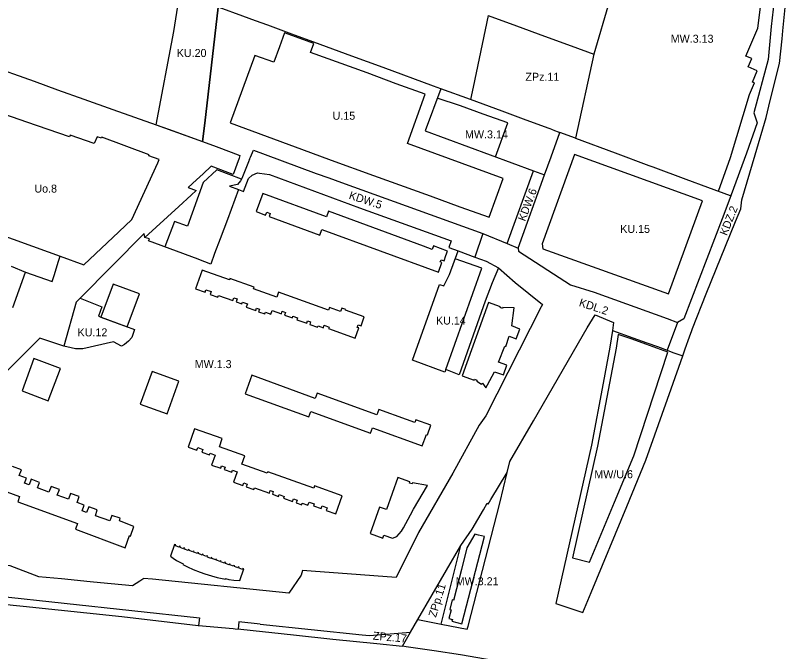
# Model space of a CAD drawing. Extents: x 7428239 to 7429836, y 5549133 to 5550853.
# Drawn here: x 7429012.7 to 7429496.4, y 5549348.1 to 5549745.6 of the extents above; entities that cross this region are included whole.
import ezdxf

# ---------------------------------------------------------------- set-up
doc = ezdxf.new("R2010")
doc.units = 0
for name, color, linetype in [('LIN_linie rozgraniczające', 7, 'Continuous'), ('LIN_nieprzekraczalna linia zabudowy', 7, 'Continuous'), ('LIN_obowiązująca linia zabudowy', 7, 'Continuous'), ('TXT_Oznaczenia Przeznaczenia', 7, 'Continuous')]:
    doc.layers.add(name, color=color, linetype=linetype)

msp = doc.modelspace()

# ---------------------------------------------------------------- linework, layer by layer
at = {"layer": 'LIN_linie rozgraniczające'}
for p, q in [((7429492.21, 5549735.89), (7429496.38, 5549776.96)), ((7429383.84, 5549754.68), (7429374.1, 5549721.36)), ((7429139.27, 5549750.82), (7429131.04, 5549678.2)), ((7429162.7, 5549742.24), (7429154.81, 5549745.13)), ((7429170.29, 5549739.46), (7429162.7, 5549742.24)), ((7429185.31, 5549733.96), (7429170.29, 5549739.46)), ((7429203.15, 5549727.43), (7429185.31, 5549733.96)), ((7429491.7, 5549730.91), (7429492.21, 5549735.89)), ((7429490.14, 5549715.52), (7429491.7, 5549730.91)), ((7429222.87, 5549720.22), (7429203.15, 5549727.43)), ((7429242.43, 5549713.03), (7429222.87, 5549720.22)), ((7429374.1, 5549721.36), (7429362.73, 5549668.82)), ((7429484.37, 5549692.54), (7429490.14, 5549715.52)), ((7429273.96, 5549701.46), (7429242.43, 5549713.03)), ((7429278.42, 5549699.82), (7429268.77, 5549673.56)), ((7429278.42, 5549699.82), (7429273.96, 5549701.46)), ((7429481.71, 5549681.92), (7429484.37, 5549692.54)), ((7429331.75, 5549680.24), (7429316.79, 5549685.74)), ((7429346.1, 5549674.98), (7429331.75, 5549680.24)), ((7429474.87, 5549658.58), (7429481.71, 5549681.92)), ((7429131.04, 5549678.2), (7429129.64, 5549666.8)), ((7429348.48, 5549674.09), (7429346.1, 5549674.98)), ((7429268.77, 5549673.56), (7429336.45, 5549648.48)), ((7429347.4, 5549657.15), (7429352.93, 5549672.44)), ((7429348.48, 5549674.09), (7429352.93, 5549672.44)), ((7429362.73, 5549668.82), (7429352.93, 5549672.44)), ((7429343.37, 5549646), (7429347.4, 5549657.15)), ((7429466.6, 5549630.37), (7429474.87, 5549658.58)), ((7429326.78, 5549600.18), (7429343.37, 5549646)), ((7429336.45, 5549648.48), (7429343.37, 5549646)), ((7429465.94, 5549624.78), (7429466.6, 5549630.37)), ((7429462.67, 5549616.76), (7429465.94, 5549624.78)), ((7428972.53, 5549619.83), (7429033.1, 5549597.79)), ((7429444.27, 5549571.62), (7429462.67, 5549616.76)), ((7429304.83, 5549609.32), (7429299.82, 5549594.64)), ((7429319.91, 5549603.04), (7429326.78, 5549600.18)), ((7429033.1, 5549597.79), (7429040.61, 5549595.06)), ((7429283.91, 5549583.75), (7429289.35, 5549598.4)), ((7429010.07, 5549588.99), (7429018.99, 5549585.19)), ((7429314.53, 5549587.88), (7429310.67, 5549578.44)), ((7429280.29, 5549576.52), (7429283.91, 5549583.75)), ((7429310.67, 5549578.44), (7429306.18, 5549567.03)), ((7429260.89, 5549530.11), (7429277.63, 5549577.44)), ((7429277.63, 5549577.44), (7429280.29, 5549576.52)), ((7429306.18, 5549567.03), (7429289.94, 5549520.95)), ((7429341.24, 5549563.45), (7429306.6, 5549495.47)), ((7429426.47, 5549553.73), (7429420, 5549536.31)), ((7429433.84, 5549544.68), (7429435.4, 5549548.7)), ((7429281.03, 5549522.62), (7429260.89, 5549530.11)), ((7429281.61, 5549524.26), (7429281.03, 5549522.62)), ((7429289.94, 5549520.95), (7429281.61, 5549524.26)), ((7429306.6, 5549495.47), (7429302.38, 5549489.44))]:
    msp.add_line(p, q, dxfattribs=at)
for points in [[(7429489.37, 5549782.19), (7429486.1, 5549749.51), (7429484.91, 5549738.63), (7429483.01, 5549718.14), (7429474.16, 5549684.69), (7429476.09, 5549678.57), (7429469.44, 5549659.48), (7429459.97, 5549633.44), (7429459.77, 5549632.89), (7429454.38, 5549618.41), (7429430.39, 5549556.05), (7429426.47, 5549553.73)], [(7429100.53, 5549677.21), (7429111.74, 5549735.61), (7429115.45, 5549759.59)], [(7429154.81, 5549745.13), (7429140.01, 5549750.55), (7429139.27, 5549750.82)], [(7429307.99, 5549745.59), (7429298.65, 5549700.82), (7429297.02, 5549693)], [(7429307.99, 5549745.59), (7429325.83, 5549739.04), (7429343.2, 5549732.68), (7429360.02, 5549726.52), (7429374.1, 5549721.36)], [(7428994.89, 5549715), (7429024.38, 5549704.45), (7429038.99, 5549699.22), (7429055.38, 5549693.36), (7429073.59, 5549686.85), (7429087.06, 5549682.03), (7429100.53, 5549677.21), (7429108.26, 5549674.45), (7429129.64, 5549666.8), (7429138.16, 5549663.61), (7429147.49, 5549660.1), (7429152.99, 5549658.04), (7429152.39, 5549656.34), (7429148.78, 5549646.13), (7429145.44, 5549647.42), (7429134.97, 5549651.4), (7429129.91, 5549646.71), (7429125.83, 5549642.94), (7429120.68, 5549638.18), (7429125.59, 5549636.17), (7429122.53, 5549633.39), (7429114.7, 5549626.25), (7429093.52, 5549606.93), (7429093.04, 5549609.25), (7429053.1, 5549568.95), (7429053.08, 5549568.93), (7429050.59, 5549566.47), (7429042.95, 5549538.83), (7429027.81, 5549543.86), (7429024.28, 5549540.35), (7428987.13, 5549503.3)], [(7429316.79, 5549685.74), (7429297.02, 5549693), (7429278.42, 5549699.82)], [(7429011.13, 5549563.04), (7429018.99, 5549585.19), (7429019.04, 5549585.21), (7429035.54, 5549579.36), (7429036.8, 5549583.05), (7429039.61, 5549592.11), (7429040.61, 5549595.06), (7429055.32, 5549589.7), (7429077.18, 5549610.42), (7429085.33, 5549618.15), (7429101.72, 5549653.59), (7429102.4, 5549655.53), (7429095.98, 5549657.9), (7429096.24, 5549658.55), (7429066.73, 5549669.47), (7429066.38, 5549668.83), (7429063.67, 5549669.83), (7429061.83, 5549665.54), (7429046.8, 5549670.88), (7429046.44, 5549669.67), (7429019.75, 5549678.94), (7428986.76, 5549690.39)], [(7429362.73, 5549668.82), (7429387.39, 5549659.69), (7429408.49, 5549651.88), (7429410.93, 5549650.98), (7429431.56, 5549643.34), (7429445.07, 5549638.33), (7429459.19, 5549633.11), (7429459.97, 5549633.44)], [(7429158.92, 5549655.81), (7429159.46, 5549657.06), (7429161.35, 5549661.39), (7429168.82, 5549658.69), (7429200.67, 5549646.93), (7429208.53, 5549644.1), (7429216.39, 5549641.27), (7429304.83, 5549609.32), (7429319.91, 5549603.04), (7429336.45, 5549648.48)], [(7429158.92, 5549655.81), (7429158.27, 5549654.14), (7429154.23, 5549643.65), (7429153.35, 5549642.28), (7429151.42, 5549640.01), (7429146.5, 5549638.97), (7429152.09, 5549636.85), (7429155.2, 5549635.68), (7429158.28, 5549643.62), (7429160.53, 5549645.87), (7429163.84, 5549647.15), (7429165.1, 5549647.05), (7429171.52, 5549646.16), (7429227.67, 5549625.35), (7429285, 5549604.79), (7429283.43, 5549600.52), (7429289.35, 5549598.4)], [(7429152.09, 5549636.85), (7429145.21, 5549618.04), (7429140.57, 5549605.93), (7429136.97, 5549596.92), (7429134.68, 5549590.23), (7429127.17, 5549593.04), (7429126.75, 5549593.2), (7429095.9, 5549604.76), (7429096.5, 5549605.98), (7429093.52, 5549606.93)], [(7429289.35, 5549598.4), (7429299.82, 5549594.64)], [(7429326.78, 5549600.18), (7429327.08, 5549598.29), (7429359.53, 5549577.16), (7429374.21, 5549572.71), (7429419.97, 5549556.13), (7429426.47, 5549553.73)], [(7429299.82, 5549594.64), (7429306.89, 5549592.1), (7429314.53, 5549587.88)], [(7429314.53, 5549587.88), (7429314.57, 5549587.85), (7429324.92, 5549578.76), (7429342.04, 5549565.02), (7429341.24, 5549563.45)], [(7429053.1, 5549568.95), (7429066.74, 5549563.45), (7429064.57, 5549557.61), (7429087.15, 5549549.25), (7429085.33, 5549544.29), (7429083.26, 5549542.05), (7429080.8, 5549540.01), (7429078.94, 5549538.9), (7429073.99, 5549541.68), (7429054.73, 5549537.35), (7429052.58, 5549537.17), (7429050.26, 5549537.24), (7429047.54, 5549537.8), (7429042.95, 5549538.83)], [(7429435.4, 5549548.7), (7429435.85, 5549549.87), (7429444.27, 5549571.62)], [(7429344.52, 5549336.6), (7429341.17, 5549337.18), (7429290.81, 5549346), (7429274.35, 5549348.49), (7429256.87, 5549351.01), (7429254.51, 5549351.36), (7429258.8, 5549358.75), (7429259.61, 5549360.15), (7429264.22, 5549368.09), (7429278.6, 5549365.24), (7429295.04, 5549361.98), (7429295.54, 5549363.92), (7429315.32, 5549440.78), (7429319.9, 5549459.86), (7429321.58, 5549466.87), (7429336.38, 5549492.35), (7429370.03, 5549550.3), (7429374.84, 5549558.59), (7429386.42, 5549553.65)], [(7429386.42, 5549553.65), (7429385.7, 5549548.72), (7429384.17, 5549538.25), (7429379.89, 5549515.74), (7429372.54, 5549477.14), (7429350.36, 5549378.16), (7429367.13, 5549372.4)], [(7429367.13, 5549372.4), (7429372.38, 5549385.05), (7429394.65, 5549438.71), (7429406.69, 5549467.74), (7429422.4, 5549512.27), (7429429.64, 5549532.77), (7429431.19, 5549537.17), (7429433.84, 5549544.68)], [(7429385.7, 5549548.72), (7429398.54, 5549544.11), (7429407.13, 5549541.02), (7429413.81, 5549538.61), (7429420, 5549536.31), (7429423.42, 5549535.04), (7429429.64, 5549532.77)], [(7429302.38, 5549489.44), (7429285.95, 5549459.46), (7429264.55, 5549422.51), (7429250.49, 5549394.41), (7429214.32, 5549397.06), (7429200.19, 5549398.1), (7429192.09, 5549398.72), (7429191.13, 5549395.83), (7429183.58, 5549384.47), (7429098.35, 5549393.23), (7429092.68, 5549393.81)], [(7429264.22, 5549368.09), (7429291.08, 5549414.35), (7429298.09, 5549424.48), (7429305.12, 5549436.69), (7429307.53, 5549440.88), (7429308.08, 5549440.1), (7429309.79, 5549443.05), (7429319.9, 5549459.86)], [(7429278.6, 5549365.24), (7429291.08, 5549414.35)], [(7428920.34, 5549411.54), (7428951.94, 5549408.14), (7428957.12, 5549407.58), (7429009.09, 5549401.82), (7429027.13, 5549395.01), (7429041.39, 5549393.62), (7429059.28, 5549391.87), (7429065.83, 5549391.23), (7429085.85, 5549389.28), (7429090.38, 5549392.28), (7429092.31, 5549393.56), (7429092.68, 5549393.81)], [(7428835.33, 5549395.39), (7428838.26, 5549395.07), (7428849.42, 5549393.84), (7428893.5, 5549389.32), (7428898.14, 5549388.85), (7428931.67, 5549385.42), (7428965.2, 5549382), (7428990.69, 5549379.21), (7429017.46, 5549376.5), (7429079.21, 5549369.9), (7429126.95, 5549364.42), (7429127.1, 5549364.41)], [(7429000.6, 5549382.84), (7429127.79, 5549369.13), (7429127.1, 5549364.41)], [(7429165.7, 5549365.22), (7429152.29, 5549366.64), (7429151.87, 5549362.13)], [(7429165.7, 5549365.22), (7429229.43, 5549358.47), (7429233.89, 5549357.99), (7429259.61, 5549360.15)], [(7429127.1, 5549364.41), (7429148.66, 5549362.42), (7429149.88, 5549362.31), (7429153.5, 5549361.98), (7429186.49, 5549358.5), (7429211.05, 5549355.87), (7429238.47, 5549353.12), (7429254.51, 5549351.36)]]:
    msp.add_lwpolyline(points, dxfattribs=at)
at = {"layer": 'LIN_nieprzekraczalna linia zabudowy'}
msp.add_line((7429360.83, 5549406.57), (7429371.46, 5549403.98), dxfattribs=at)
for points in [[(7429452.01, 5549635.77), (7429459.42, 5549656.85), (7429471.36, 5549696.17), (7429474.49, 5549703.54), (7429473.26, 5549703.98), (7429476.25, 5549711.05), (7429470.57, 5549713.46), (7429472.74, 5549718.65), (7429469.16, 5549720.19), (7429476.56, 5549737.72), (7429481.57, 5549777.29)], [(7429100.53, 5549677.21), (7429129.64, 5549666.8), (7429131.04, 5549678.2), (7429139.27, 5549750.82), (7429130.67, 5549753.98), (7429115.45, 5549759.59)], [(7429307.99, 5549745.59), (7429325.83, 5549739.04), (7429343.2, 5549732.68), (7429360.02, 5549726.52), (7429374.1, 5549721.36)], [(7429177.65, 5549725.97), (7429174.11, 5549716.36), (7429162.2, 5549720.63), (7429146.8, 5549678.5), (7429183.43, 5549664.87), (7429191.45, 5549662), (7429209.94, 5549655.2), (7429236.52, 5549645.67), (7429271.76, 5549632.88), (7429290.36, 5549626), (7429308.72, 5549619.46), (7429317.38, 5549643.62), (7429257.7, 5549665.53), (7429268.72, 5549696.4), (7429250.52, 5549702.87), (7429232.48, 5549709.68), (7429197.13, 5549722.42), (7429199.1, 5549728.03), (7429180.87, 5549734.69), (7429177.65, 5549725.97)], [(7429312.66, 5549657.3), (7429320.28, 5549678.5), (7429305.01, 5549683.98), (7429290.8, 5549689.12), (7429276.25, 5549693.92)], [(7429341.86, 5549602.8), (7429342.32, 5549599.84), (7429420.69, 5549571.56), (7429441.95, 5549629.76), (7429362.09, 5549658.74), (7429341.86, 5549602.8)], [(7429153.95, 5549643.21), (7429138.58, 5549649.08), (7429129.94, 5549641.28), (7429120.21, 5549613.98), (7429111.97, 5549616.91), (7429105.94, 5549601)], [(7429281.61, 5549524.26), (7429304.09, 5549587.57), (7429287.54, 5549593.53)], [(7429053.07, 5549568.96), (7429050.59, 5549566.47), (7429042.95, 5549538.83)], [(7429399.03, 5549470.44), (7429420.38, 5549535.23), (7429406.68, 5549540.08), (7429398.1, 5549543.23), (7429389.39, 5549546.3), (7429388.12, 5549537.59), (7429376.46, 5549476.33), (7429360.83, 5549406.57)], [(7429371.46, 5549403.98), (7429386.99, 5549441.41), (7429399.03, 5549470.44)], [(7429284.99, 5549374.15), (7429283.52, 5549368.72), (7429285.69, 5549368.16), (7429285.42, 5549367.09), (7429291.71, 5549365.47), (7429305.76, 5549419.96), (7429302.1, 5549420.85), (7429299.81, 5549421.41), (7429294.82, 5549412.83)], [(7429294.82, 5549412.83), (7429291.47, 5549399.34), (7429286.67, 5549380.73), (7429286.52, 5549380.14), (7429285.61, 5549380.38), (7429284.05, 5549374.37), (7429284.99, 5549374.15)]]:
    msp.add_lwpolyline(points, dxfattribs=at)
at = {"layer": 'LIN_obowiązująca linia zabudowy'}
for points in [[(7429169.03, 5549620.85), (7429169.66, 5549622.56), (7429171.85, 5549621.75), (7429171.21, 5549620.03), (7429202.79, 5549608.31), (7429204.08, 5549611.85), (7429277.12, 5549585.22), (7429279.2, 5549591.15), (7429278.14, 5549591.53), (7429278.66, 5549592.93), (7429280.49, 5549592.26), (7429281.64, 5549595.65), (7429282.61, 5549598.29), (7429273.89, 5549601.52), (7429273.12, 5549599.3), (7429267.67, 5549601.33), (7429208.31, 5549623.3), (7429207.01, 5549619.79), (7429167.25, 5549634.41), (7429163.09, 5549623.09)], [(7429125.29, 5549574.68), (7429131.16, 5549572.58), (7429131.74, 5549574.2), (7429134.92, 5549573.06), (7429134.28, 5549571.26), (7429139.13, 5549569.53), (7429139.51, 5549570.6), (7429148.5, 5549567.38), (7429149.14, 5549569.16), (7429151.27, 5549568.4), (7429150.64, 5549566.65), (7429154.23, 5549565.36), (7429154.6, 5549566.38), (7429157.66, 5549565.29), (7429156.93, 5549563.25), (7429162.8, 5549561.14), (7429163.37, 5549562.73), (7429165.21, 5549562.07), (7429164.61, 5549560.39), (7429168.45, 5549559.02), (7429168.84, 5549560.09), (7429172.22, 5549558.88), (7429173.05, 5549561.21), (7429178.84, 5549559.13), (7429179.4, 5549560.7), (7429181.49, 5549559.95), (7429180.88, 5549558.25), (7429185.71, 5549556.52), (7429186.1, 5549557.62), (7429188.93, 5549556.6), (7429188.52, 5549555.46), (7429194.72, 5549553.24), (7429195.26, 5549554.75), (7429197.15, 5549554.08), (7429196.58, 5549552.47), (7429201.51, 5549550.71), (7429201.83, 5549551.61), (7429205.1, 5549550.43), (7429205.65, 5549551.97), (7429208.67, 5549550.89), (7429208.3, 5549549.87), (7429225.04, 5549543.87), (7429227.34, 5549550.27), (7429226.2, 5549550.68), (7429226.75, 5549552.22), (7429228.62, 5549551.55), (7429230.66, 5549557.24), (7429218.92, 5549561.44), (7429219.04, 5549561.77), (7429216.58, 5549562.65), (7429215.84, 5549560.57), (7429208.92, 5549563.05), (7429208.32, 5549561.37), (7429177.08, 5549572.56), (7429175.96, 5549569.45), (7429161.44, 5549574.65), (7429161.85, 5549575.8), (7429146.66, 5549581.24), (7429146.33, 5549580.31), (7429129.42, 5549586.37)], [(7429073.75, 5549577.75), (7429066.05, 5549557.05), (7429082.47, 5549550.98), (7429090.19, 5549571.59)], [(7429291.89, 5549520.31), (7429299.33, 5549517.65), (7429299.57, 5549518.21), (7429301.09, 5549517.57), (7429300.93, 5549517.11), (7429303.8, 5549515.09), (7429304.61, 5549515.81), (7429306.54, 5549512.84), (7429307.72, 5549514.69), (7429311.94, 5549522.91), (7429317.65, 5549520.95), (7429319.81, 5549526.97), (7429314.6, 5549529), (7429318.4, 5549538.85), (7429319.19, 5549538.61), (7429321.25, 5549545.11), (7429325.65, 5549543.55), (7429327.82, 5549549.61), (7429322.77, 5549551.58), (7429324.28, 5549562.92), (7429317.2, 5549563.07), (7429317.07, 5549562.49), (7429315.6, 5549563), (7429315.72, 5549563.59), (7429308.31, 5549566.26)], [(7429024.18, 5549531.22), (7429016.91, 5549511.03), (7429033.2, 5549504.73), (7429040.78, 5549524.93)], [(7429098.02, 5549523.07), (7429090.51, 5549502.67), (7429107.41, 5549496.54), (7429114.7, 5549516.95)], [(7429156.22, 5549509.18), (7429195.96, 5549494.72), (7429197.21, 5549498.15), (7429234.5, 5549484.48), (7429235.73, 5549487.84), (7429266.83, 5549476.57), (7429269.54, 5549483.73), (7429270.06, 5549483.58), (7429272.23, 5549489.53), (7429262.86, 5549492.94), (7429262.25, 5549491.25), (7429256.96, 5549493.18), (7429239.8, 5549499.42), (7429238.57, 5549496.05), (7429201.27, 5549509.63), (7429200.05, 5549506.29), (7429160.41, 5549520.71)], [(7429120.61, 5549475.84), (7429126.05, 5549473.9), (7429126.62, 5549475.48), (7429129.77, 5549474.35), (7429129.18, 5549472.7), (7429133.98, 5549470.99), (7429134.34, 5549471.99), (7429137.47, 5549470.88), (7429135.24, 5549464.63), (7429140.95, 5549462.59), (7429141.5, 5549464.13), (7429143.65, 5549463.36), (7429143.08, 5549461.76), (7429147.81, 5549460.07), (7429148.28, 5549461.4), (7429151.27, 5549460.34), (7429148.99, 5549453.96), (7429154.83, 5549451.87), (7429155.41, 5549453.48), (7429157.47, 5549452.74), (7429156.88, 5549451.09), (7429161.69, 5549449.37), (7429162.07, 5549450.44), (7429171.33, 5549447.13), (7429171.9, 5549448.71), (7429173.82, 5549448.03), (7429173.25, 5549446.43), (7429177.11, 5549445.05), (7429177.49, 5549446.13), (7429180.65, 5549445), (7429180.25, 5549443.87), (7429185.89, 5549441.85), (7429186.47, 5549443.48), (7429188.75, 5549442.66), (7429188.14, 5549440.96), (7429191.55, 5549439.74), (7429191.94, 5549440.83), (7429195.45, 5549439.57), (7429196.12, 5549441.44), (7429199.28, 5549440.31), (7429198.86, 5549439.13), (7429203.68, 5549437.41), (7429204.26, 5549439.04), (7429207.52, 5549437.88), (7429206.92, 5549436.2), (7429212.85, 5549434.08), (7429216.9, 5549445.43), (7429199.65, 5549451.6), (7429199.13, 5549450.15), (7429170.32, 5549460.44), (7429169.95, 5549459.53), (7429154.11, 5549465.24), (7429155.96, 5549470.35), (7429140.14, 5549476.09), (7429141.91, 5549481.14), (7429124.66, 5549487.16)], [(7429251.7, 5549456.81), (7429244.55, 5549436.85), (7429240.15, 5549438.36), (7429234.31, 5549421.81), (7429242.3, 5549418.94), (7429242.94, 5549420.72), (7429248.34, 5549418.82), (7429250.92, 5549420.04), (7429253.82, 5549423.29), (7429255.06, 5549425.46), (7429259.51, 5549433.58), (7429261.42, 5549437.13), (7429270.14, 5549451.92), (7429260.69, 5549453.55), (7429260.48, 5549452.79), (7429258.88, 5549453.36), (7429259.17, 5549454.16)], [(7429112.16, 5549414.91), (7429109.6, 5549407.59), (7429111.24, 5549406.41), (7429113.3, 5549405.03), (7429115.37, 5549403.85), (7429117.49, 5549402.85), (7429117.33, 5549402.51), (7429120.12, 5549401.09), (7429123.8, 5549399.41), (7429128.03, 5549397.62), (7429130.97, 5549396.6), (7429135.14, 5549395.37), (7429138.75, 5549394.42), (7429143.83, 5549393.35), (7429143.99, 5549393.79), (7429146, 5549393.04), (7429149.13, 5549392.65), (7429152.92, 5549392.4), (7429155.48, 5549399.77), (7429154.85, 5549400.01), (7429154.6, 5549399.34), (7429152.39, 5549400.16), (7429152.57, 5549400.66), (7429151.88, 5549400.92), (7429151.67, 5549400.33), (7429149.54, 5549401.12), (7429149.72, 5549401.62), (7429149.05, 5549401.87), (7429148.86, 5549401.35), (7429146.68, 5549402.16), (7429146.84, 5549402.58), (7429146.36, 5549402.75), (7429146.21, 5549402.35), (7429143.94, 5549403.18), (7429144.1, 5549403.63), (7429143.5, 5549403.85), (7429143.3, 5549403.33), (7429141.12, 5549404.14), (7429141.29, 5549404.59), (7429140.75, 5549404.79), (7429140.58, 5549404.32), (7429138.28, 5549405.17), (7429138.45, 5549405.63), (7429137.94, 5549405.82), (7429137.8, 5549405.44), (7429135.44, 5549406.31), (7429135.56, 5549406.61), (7429135.05, 5549406.8), (7429134.86, 5549406.28), (7429132.63, 5549407.11), (7429132.83, 5549407.63), (7429132.28, 5549407.84), (7429132.11, 5549407.39), (7429129.91, 5549408.2), (7429130.07, 5549408.63), (7429129.52, 5549408.83), (7429129.36, 5549408.38), (7429127.05, 5549409.23), (7429127.2, 5549409.66), (7429126.58, 5549409.89), (7429126.38, 5549409.37), (7429124.11, 5549410.21), (7429124.27, 5549410.64), (7429123.81, 5549410.8), (7429123.62, 5549410.28), (7429121.28, 5549411.14), (7429121.46, 5549411.62), (7429120.82, 5549411.86), (7429120.61, 5549411.3), (7429118.4, 5549412.11), (7429118.58, 5549412.58), (7429117.97, 5549412.8), (7429117.79, 5549412.34), (7429115.66, 5549413.12), (7429115.83, 5549413.69), (7429115.22, 5549413.87), (7429115.05, 5549413.31), (7429112.62, 5549414.05), (7429112.82, 5549414.71)]]:
    msp.add_lwpolyline(points, close=True, dxfattribs=at)
msp.add_lwpolyline([(7428983.36, 5549456.62), (7429015.26, 5549444.94), (7429014.12, 5549441.65), (7429051.37, 5549428.07), (7429050.17, 5549424.48), (7429081.17, 5549412.9), (7429083.89, 5549420.49), (7429084.49, 5549420.21), (7429086.62, 5549426.29), (7429077.62, 5549429.72), (7429078.07, 5549431.36), (7429072.95, 5549433.16), (7429071.7, 5549429.67), (7429062.73, 5549432.94), (7429063.83, 5549436.6), (7429058.48, 5549438.51), (7429057.11, 5549435), (7429054.45, 5549436), (7429055.57, 5549439.59), (7429051.14, 5549441.23), (7429052.51, 5549444.94), (7429047.15, 5549446.92), (7429045.78, 5549443.21), (7429038.78, 5549445.8), (7429040.1, 5549449.37), (7429034.9, 5549451.28), (7429033.59, 5549447.72), (7429026.53, 5549450.32), (7429027.8, 5549453.76), (7429022.45, 5549455.73), (7429021.18, 5549452.29), (7429018.35, 5549453.33), (7429019.49, 5549456.42), (7429015.05, 5549458.04), (7429016.38, 5549461.7), (7429010.86, 5549463.71)], dxfattribs=at)

# ---------------------------------------------------------------- texts
at = {"layer": 'TXT_Oznaczenia Przeznaczenia'}
for s, p in [('MW.3.13', (7429422.14, 5549728.55)), ('KU.20', (7429113.49, 5549719.65)), ('ZPz.11', (7429331.36, 5549704.78)), ('U.15', (7429210.86, 5549680.43)), ('MW.3.14', (7429293.61, 5549668.77)), ('Uo.8', (7429024.51, 5549634.89)), ('KU.15', (7429390.61, 5549609.7)), ('KU.14', (7429275.47, 5549552.45)), ('KU.12', (7429051.5, 5549545.04)), ('MW.1.3', (7429124.7, 5549525.21)), ('MW/U.6', (7429374.42, 5549456.37)), ('MW.3.21', (7429287.8, 5549389.5))]:
    msp.add_text(s, height=5, dxfattribs=at).set_placement(p)
for s, rotation, p in [('KDW.6', 69.1525, (7429331.14, 5549616.58)), ('KDW.5', 341.9358, (7429220.67, 5549631.16)), ('KDZ.2', 68.3345, (7429457.18, 5549607.64)), ('KDL.2', 341.9358, (7429364.43, 5549564.1)), ('ZPp.11', 73.0753, (7429275.41, 5549369.05)), ('ZPz.17', 354.9263, (7429235.93, 5549355.52))]:
    msp.add_text(s, height=5, rotation=rotation, dxfattribs=at).set_placement(p)

doc.saveas('drawing.dxf')
